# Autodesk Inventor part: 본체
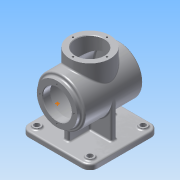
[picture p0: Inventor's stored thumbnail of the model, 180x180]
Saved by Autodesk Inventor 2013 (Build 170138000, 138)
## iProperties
Created: 2015-07
Part Number: 본체
Material: 알루미늄 6061
Document SubType Name: Modeling
Designer: ST3
Density: 2.71 g/cm^3
Mass: 1277.74 g
Surface Area: 1267.64 cm^2
Volume: 471.49 cm^3
Author: ST3
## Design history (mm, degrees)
sketch "스케치1"
  geometry: L1 (0, 0)-(128.399, 0); L2 (0, 27)-(0, 38); L3 (0, 38)-(7, 38); L4 (7, 38)-(7, 45); L5 (0, 27)-(14, 27); L6 (117, 45)-(117, 0); L7 (110, 40)-(110, 0); L8 (14, 27)-(14, 40); L9 (14, 40)-(110, 40); L10 (7, 45)-(117, 45)
  constraints: 20 end point, 5 perpendicular, 3 parallel, 2 point on line, 1 horizontal
  dimensions: "d0" = 54 diameter of L5 L1; "d3" = 76 diameter of L3 L1; "d8" = 80 diameter of L9 L1; "d9" = 14 distance between parallel lines of L8 L2; "d10" = 96 distance between parallel lines of L7 L8; "d11" = 7 distance between parallel lines of L6 L7; "d12" = 7 distance between parallel lines of L2 L4; "d13" = 90 diameter of L10 L1; "d14" = 0 distance from line of L1.start L2
revolve "회전1" sketch "스케치1" stored, may be unused: angle "d15" = 90 deg
fillet "모깎기1" dims "d16" = 3
chamfer "모따기1" distance "d17" = 1; stored, may be unused: second distance "d18" = 2, angle "d19" = 45 deg
fillet "모깎기2" dims "d20" = 3
fillet "모깎기3" dims "d21" = 3
node "작업 평면1"
sketch "스케치2"
  geometry: L1 (127, 65)-(-3, 65); L2 (-3, 65)-(-3, -65); L3 (-3, -65)-(127, -65); L4 (127, -65)-(127, 65); L5 (114, -45)-(114, 45) reference; L6 (10, 45)-(10, -45) reference; L7 (7, -42)-(7, 42) reference; 1 further point
  constraints: 8 end point, 2 parallel, 1 horizontal, 1 perpendicular
  dimensions: "d23" = 130 distance of L3.end L1.start; "d25" = 130 distance of L1.start L1.end; "d26" = 65 distance from line of point (0, 0) L1; "d27" = 10 distance between parallel lines of L7 L2
extrude "돌출1" join sketch "스케치2" distance "d28" = 10; taper "d29" = 0 deg
fillet "모깎기4" dims "d30" = 15
sketch "스케치3"
  geometry: C1 r 7.5 at (12, 50); C2 r 7.5 at (112, 50); C3 r 7.5 at (12, -50); C4 r 7.5 at (112, -50); A1 r 15 centre (112, -50) between (112, -65) and (127, -50) reference; A2 r 15 centre (112, 50) between (127, 50) and (112, 65) reference; A3 r 15 centre (12, 50) between (12, 65) and (-3, 50) reference; A4 r 15 centre (12, -50) between (-3, -50) and (12, -65) reference; 1 further point
  constraints: 4 centre point, 4 coincident
  dimensions: "d31" = 15 diameter of C1; "d33" = 15 diameter of C2; "d34" = 15 diameter of C4; "d35" = 15 diameter of C3
extrude "돌출2" join sketch "스케치3" distance "d36" = 3; taper "d37" = 0 deg
sketch "스케치4"
  geometry: C1 r 7.5 at (0, 0) reference; C2 r 5 at (0, 0); 1 further point
  constraints: 1 centre point, 1 coincident
  dimensions: "d38" = 10 diameter of C2
extrude "돌출3" cut sketch "스케치4" stored distance "d40" = 3; taper "d41" = 0 deg
node "작업 평면2"
fillet "모깎기5" dims "d42" = 3
fillet "모깎기6" dims "d43" = 3
sketch "스케치5"
  geometry: L1 (124, 50)-(124, -50) reference; L2 (0, 0)-(124, 0); L3 (62, 65.262)-(62, -65.262); L4 (127, -50)-(127, 50) reference; L5 (17, 5)-(57, 5); L6 (57, 5)-(57, 45); L7 (57, 45)-(67, 45); L8 (67, 45)-(67, 5); L9 (67, 5)-(107, 5); L10 (107, 5)-(107, -5); L11 (107, -5)-(67, -5); L12 (67, -5)-(67, -45); L13 (67, -45)-(57, -45); L14 (57, -45)-(57, -5); L15 (57, -5)-(17, -5); L16 (17, -5)-(17, 5)
  constraints: 28 end point, 7 perpendicular, 5 parallel, 3 collinear, 1 midpoint
  dimensions: "d44" = 65 distance between parallel lines of L4 L3; "d45" = 10 distance between parallel lines of L8 L6; "d46" = 10 distance between parallel lines of L15 L5; "d47" = 10 distance between parallel lines of L12 L14; "d48" = 10 distance between parallel lines of L9 L11; "d49" = 90 distance between parallel lines of L10 L16; "d50" = 90 distance between parallel lines of L13 L7; "d51" = 45 distance between parallel lines of L3 L16; "d52" = 45 distance between parallel lines of L2 L13; "d53" = 5 distance between parallel lines of L3 L6; "d54" = 5 distance between parallel lines of L2 L5
extrude "돌출4" join sketch "스케치5" stored distance "d55" = 3; taper "d56" = 0 deg
fillet "모깎기7" dims "d57" = 3
fillet "모깎기8" dims "d58" = 3
fillet "모깎기9" dims "d59" = 3
fillet "모깎기10" dims "d60" = 3
node "작업 평면4"
sketch "스케치7"
  geometry: L1 (7, -42)-(7, 42) reference; C1 r 38 at (62, 0); 1 further point
  constraints: 1 centre point
  dimensions: "d67" = 76 diameter of C1; "d69" = 0 vertical distance of point (0, 0) C1.centre; "d70" = 55 distance from line of L1 C1.centre
extrude "돌출5" join sketch "스케치7" stored distance "d71" = 3; taper "d72" = 0 deg
fillet "모깎기11" dims "d73" = 3
sketch "스케치8"
  geometry: C1 r 38 at (0, 0) reference; C2 r 27 at (0, 0); 1 further point
  constraints: 1 centre point, 1 coincident
  dimensions: "d74" = 54 diameter of C2
extrude "돌출6" cut sketch "스케치8" distance "d76" = 59.75; taper "d77" = 0 deg
chamfer "모따기2" distance "d78" = 1; stored, may be unused: second distance "d79" = 2, angle "d80" = 45 deg
sketch "스케치9" dims "d81" = 64
  geometry: L1 (0, 0)-(-62, 0); C1 r 28 at (0, 0) reference; C2 r 3.197 at (-32, 0)
  constraints: 2 end point, 1 centre point, 1 coincident, 1 horizontal, 1 horizontal alignment, 1 point on line, 2 other
hole "구멍1" sketch "스케치9" at (-32, 0) diameter "d83" = 3.242; stored, may be unused: countersink angle "d87" = 90 deg, drill point angle "d89" = 118 deg; dims "d84" = 8, "d85" = 4, "d86" = 2, "d88" = 10
sketch "스케치10" dims "d93" = 64
  geometry: L1 (0, 0)-(70.36, 0); C1 r 28 at (0, 0) reference; C2 r 3.938 at (32, 0)
  constraints: 2 end point, 1 centre point, 1 coincident, 1 horizontal, 1 horizontal alignment, 1 point on line, 2 other
hole "구멍2" sketch "스케치10" at (32, 0) diameter "d95" = 3.242; stored, may be unused: countersink angle "d99" = 90 deg, drill point angle "d101" = 118 deg; dims "d96" = 8, "d97" = 4, "d98" = 2, "d100" = 10
sketch "스케치11"
  geometry: L1 (-25, -10)-(-25, 10); L2 (-25, 10)-(25, 10); L3 (25, 10)-(25, -10); L4 (25, -10)-(-25, -10); C1 r 42 at (0, 0) reference
  constraints: 1 horizontal, 2 other
  dimensions: "d105" = 50 distance between parallel lines of L3 L1; "d107" = 20 distance between parallel lines of L2 L4; "d108" = 25 distance from line of C1.centre L1; "d109" = 10 distance from line of C1.centre L4
feature "엠보싱1" sketch "스케치11" dims "d0" = 54, "d3" = 76, "d8" = 80, "d9" = 14, "d10" = 96, "d11" = 7, "d12" = 7, "d13" = 90, "d14" = 0, "d20" = 3, "d110" = 0.5, "d111" = 0
fillet "모깎기12" dims "d112" = 3
fillet "모깎기13" dims "d113" = 3
sketch "스케치12"
  geometry: L1 (-107, 40)-(-17, 40) reference; L2 (-107, -40)-(-17, -40) reference; 1 further point
node "솔리드1"
mirror "대칭1"
mirror "대칭2"
pattern_circular "원형 패턴1" dims angle "d91" = 360 deg
pattern_circular "원형 패턴2" dims angle "d103" = 360 deg
node "투영된 루프1"
other parameters: "d22" = -78, "d66" = 62
